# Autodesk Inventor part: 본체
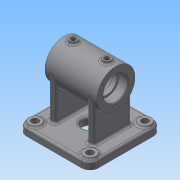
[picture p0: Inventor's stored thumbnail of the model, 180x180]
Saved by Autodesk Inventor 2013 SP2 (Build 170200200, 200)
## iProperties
Created: 2025-10
Part Number: 본체
Material: Generic
Document SubType Name: Modeling
Designer: a
Density: 1 g/cm^3
Author: a
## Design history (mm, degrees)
sketch "스케치1"
  geometry: L1 (47, 10)-(-47, 10); L2 (-47, 10)-(-47, 0); L3 (-47, 0)-(47, 0); L4 (47, 0)-(47, 10); 2 further points
  constraints: 8 end point, 2 midpoint, 2 parallel, 1 horizontal, 1 perpendicular, 1 vertical alignment
  dimensions: "d0" = 94 distance of L1.start L1.end; "d2" = 10 distance of L3.end L1.start
extrude "돌출1" new body sketch "스케치1" stored distance "d3" = 94; taper "d4" = 0 deg
sketch "스케치2"
  geometry: L1 (10, -47)-(0, -47) reference; L2 (0, -47)-(0, 47) reference; L3 (0, 47)-(10, 47) reference; L4 (10, 47)-(10, -47) reference; C1 r 25 at (66, 0); 2 further points
  constraints: 1 centre point, 1 horizontal alignment, 1 midpoint
  dimensions: "d5" = 50 diameter of C1; "d7" = 66 distance from line of L2 C1.centre
extrude "돌출2" join sketch "스케치2" stored distance "d8" = 68; taper "d9" = 0 deg
sketch "스케치3"
  geometry: L1 (0, 94)-(94, 94) reference; L2 (94, 94)-(94, 0) reference; L3 (94, 0)-(0, 0) reference; L4 (0, 0)-(0, 94) reference; L5 (68, 72)-(76, 72); L6 (76, 72)-(76, 22); L7 (76, 22)-(68, 22); L8 (68, 22)-(68, 72); 2 further points
  constraints: 8 end point, 2 parallel, 1 horizontal, 1 horizontal alignment, 1 midpoint, 1 perpendicular
  dimensions: "d10" = 8 distance of L5.start L5.end; "d12" = 50 distance of L5.end L6.end; "d13" = 21 distance from line of L8 point (47, 47)
extrude "돌출3" join sketch "스케치3" distance "d14" = 56; taper "d15" = 0 deg
node "작업 평면2"
  node "작업 평면1"
sketch "스케치4"
  geometry: L1 (-34, 25)-(-34, -25) reference; C1 r 5 at (-22, 0); 1 further point
  constraints: 1 centre point, 1 horizontal alignment
  dimensions: "d17" = 12 distance from line of C1.centre L1; "d18" = 10 diameter of C1
extrude "돌출4" join sketch "스케치4" distance "d19" = 10; taper "d20" = 0 deg
node "작업 평면4"
  node "작업 평면3"
sketch "스케치5"
  geometry: C1 r 6 at (0, 0); 1 further point
  constraints: 1 centre point, 1 coincident
  dimensions: "d22" = 12 diameter of C1
extrude "돌출5" join sketch "스케치5" distance "d23" = 10; taper "d24" = 0 deg
sketch "스케치6"
  geometry: C1 r 8 at (11, 83); 2 further points
  constraints: 1 centre point, 1 coincident
  dimensions: "d25" = 36 horizontal distance of point (47, 47) point (11, 83); "d26" = 36 horizontal distance of point (47, 47) point (11, 83); "d27" = 16 diameter of C1
extrude "돌출6" join sketch "스케치6" distance "d28" = 2; taper "d29" = 0 deg
hole "구멍1" diameter "d32" = 9; stored, may be unused: countersink angle "d36" = 90 deg, drill point angle "d38" = 118 deg; dims "d30" = 10, "d31" = 10, "d33" = 6, "d34" = 4, "d35" = 2, "d37" = 20
fillet "모깎기1" dims "d39" = 11
sketch "스케치7"
  geometry: L1 (21, 10)-(21, 41) reference; L2 (21, 41)-(6, 41) reference; L3 (6, 41)-(6, 38) reference; L4 (6, 38)-(-6, 38) reference; L5 (-6, 38)-(-6, 41) reference; L6 (-6, 41)-(-21, 41) reference; L7 (-21, 41)-(-21, 10) reference; L8 (-21, 10)-(21, 10) reference; L9 (-34, 41)-(-34, 91) reference; L10 (-34, 91)-(-27, 91) reference; L11 (-27, 91)-(-27, 94) reference; L12 (-27, 94)-(-17, 94) reference; L13 (-17, 94)-(-17, 91) reference; L14 (-17, 91)-(17, 91) reference; L15 (17, 91)-(17, 94) reference; L16 (17, 94)-(27, 94) reference; L17 (27, 94)-(27, 91) reference; L18 (27, 91)-(34, 91) reference; L19 (34, 91)-(34, 41) reference; L20 (34, 41)-(29, 41) reference; L21 (29, 41)-(29, 10) reference; L22 (29, 10)-(47, 10) reference; L23 (47, 10)-(47, 0) reference; L24 (47, 0)-(-47, 0) reference; L25 (-47, 0)-(-47, 10) reference; L26 (-47, 10)-(-29, 10) reference; L27 (-29, 10)-(-29, 41) reference; L28 (-29, 41)-(-34, 41) reference; L29 (-34, 66)-(34, 66); L30 (-34, 66)-(-34, 82); L31 (-34, 82)-(-22.3, 82); L32 (-22, 81.7)-(-22, 79.5); L33 (-22, 79.5)-(-16.258, 79.5); L34 (-16.258, 79.5)-(-5.696, 85.598); L35 (-4.196, 86)-(0, 86); L36 (0, 86)-(0, 66); L37 (34, 66)-(34, 82); L38 (34, 41)-(34, 91); L39 (22, 81.7)-(22, 79.5); L40 (34, 82)-(22.3, 82); L41 (22, 79.5)-(16.258, 79.5); L42 (16.258, 79.5)-(5.696, 85.598); L43 (4.196, 86)-(0, 86); A1 r 0.3 centre (22.3, 81.7) between (22.3, 82) and (22, 81.7); A2 r 0.3 centre (-22.3, 81.7) between (-22, 81.7) and (-22.3, 82); A3 r 3 centre (-4.196, 83) between (-4.196, 86) and (-5.696, 85.598); A4 r 3 centre (4.196, 83) between (5.696, 85.598) and (4.196, 86); 5 further points
  constraints: 30 end point, 10 point on line, 8 point on circle, 8 tangent, 5 symmetric about line, 4 centre point, 3 midpoint, 2 equal radius, 2 parallel, 2 perpendicular, 1 vertical
  dimensions: "d40" = 5 distance of point (-5, 86) L35.end; "d42" = 12 distance of L30.end point (-22, 82); "d43" = 30 deg angle of L29 L34; "d44" = 13.5 distance between parallel lines of L29 L33; "d45" = 16 distance between parallel lines of L31 L29; "d46" = 20 distance between parallel lines of L29 L35; "d48" = 0.3 radius of A1; "d49" = 3 radius of A3
revolve "회전1" sketch "스케치7" stored, may be unused: angle "d47" = 90 deg
hole "구멍2" diameter "d52" = 20; stored, may be unused: countersink angle "d56" = 90 deg, drill point angle "d58" = 118 deg; dims "d50" = 10, "d51" = 10, "d53" = 6, "d54" = 4, "d55" = 2, "d57" = 20
hole "구멍3" diameter "d61" = 5.188; stored, may be unused: countersink angle "d65" = 90 deg, drill point angle "d67" = 118 deg; dims "d59" = 10, "d60" = 10, "d62" = 6, "d63" = 6.6, "d64" = 2, "d66" = 20
hole "구멍4" diameter "d70" = 5.188; stored, may be unused: countersink angle "d74" = 90 deg, drill point angle "d76" = 118 deg; dims "d68" = 10, "d69" = 10, "d71" = 6, "d72" = 6.6, "d73" = 2, "d75" = 20
sketch "스케치8" dims "d77" = 41
  geometry: C1 r 16 at (0, 0) reference; C2 r 25 at (0, 0) reference; 5 further points
  constraints: 2 vertical alignment, 1 coincident, 6 other
  dimensions: "d80" = 360 deg dimension on C1.centre point (0, -20.5) (derived)
hole "구멍5" sketch "스케치8" at (0, -20.5), (17.754, 10.25), (-17.754, 10.25) diameter "d82" = 3.242; stored, may be unused: countersink angle "d86" = 90 deg, drill point angle "d88" = 118 deg; dims "d83" = 8, "d84" = 6.6, "d85" = 2, "d87" = 10
fillet "모깎기2" dims "d95" = 3
chamfer "모따기1" distance "d96" = 1; stored, may be unused: second distance "d97" = 2, angle "d98" = 45 deg
fillet "모깎기3" dims "d99" = 3
fillet "모깎기4" dims "d100" = 3
fillet "모깎기5" dims "d101" = 3
node "작업 평면6"
sketch "스케치11"
  geometry: L1 (-57.276, 67)-(57.276, 67); L2 (57.276, 67)-(57.276, 65); L3 (57.276, 65)-(-57.276, 65); L4 (-57.276, 65)-(-57.276, 67); L5 (-36, 0)-(36, 0) reference; 3 further points
  constraints: 2 midpoint, 1 vertical alignment, 2 other
  dimensions: "d108" = 65 distance between parallel lines of L3 L5; "d109" = 2 distance of L1.end L2.end
feature "엠보싱2" sketch "스케치11" dims "d0" = 94, "d2" = 10, "d10" = 8, "d12" = 50, "d13" = 21, "d110" = 0.5, "d111" = 0
node "솔리드1"
mirror "대칭1"
mirror "대칭2"
mirror "대칭3"
mirror "대칭4"
pattern_linear "직사각형 패턴1" dims "d91" = 72, "d94" = 72
node "절단 모서리 투영1"
node "절단 모서리 투영2"
node "절단 모서리 투영3"
other parameters: "d16" = 3, "d21" = -3, "d107" = 75.75
